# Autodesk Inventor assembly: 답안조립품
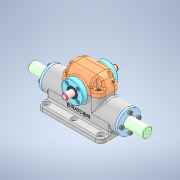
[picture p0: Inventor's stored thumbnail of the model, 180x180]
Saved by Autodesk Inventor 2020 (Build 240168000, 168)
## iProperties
Created: 2024-08
Part Number: 답안조립품
Document SubType Name: Assembly
Designer: oem
Author: oem
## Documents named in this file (13)
- C:\Users\oem\Desktop\640804V1002\답안조립품.iam
- C:\Users\oem\Desktop\640804V1002\본체.ipt
- C:\Users\oem\Desktop\640804V1002\오일레스 부시.ipt
- C:\Users\oem\Desktop\640804V1002\부시 커버.ipt
- C:\Users\oem\Desktop\640804V1002\스프링 와셔 M4.ipt
- C:\Users\oem\Desktop\640804V1002\육각 소켓 머리 볼트 M4x10.ipt
- C:\Users\oem\Desktop\640804V1002\랙.ipt
- C:\Users\oem\Desktop\640804V1002\깊은 홈 볼 베어링 6901.ipt
- C:\Users\oem\Desktop\640804V1002\칼라.ipt
- C:\Users\oem\Desktop\640804V1002\피니언.ipt
- C:\Users\oem\Desktop\640804V1002\윗커버.ipt
- C:\Users\oem\Desktop\640804V1002\베어링 커버.ipt
- C:\Users\oem\Desktop\640804V1002\오일실 12 22 7.ipt
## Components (1 placed, 1 different names)
1. 피니언:1 — 각도:2
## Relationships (1: Angle 1)
- 각도:2 [Angle]: 피니언:1
